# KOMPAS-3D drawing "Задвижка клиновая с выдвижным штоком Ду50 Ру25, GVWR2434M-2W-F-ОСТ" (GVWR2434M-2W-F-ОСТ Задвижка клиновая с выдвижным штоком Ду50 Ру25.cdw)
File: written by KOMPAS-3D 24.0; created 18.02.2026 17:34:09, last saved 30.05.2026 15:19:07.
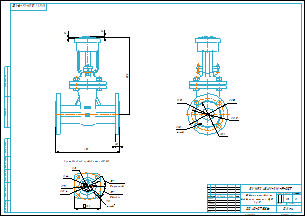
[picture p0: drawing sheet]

Document properties: Автор: R2D2; Форматы листов документа: A2; Полное имя файла: GVWR2434M-2W-F-ОСТ Задвижка клиновая с выдвижным штоком Ду50 Ру25.m3d; Масса: 13; Наименование: Задвижка клиновая с выдвижным штоком Ду50 Ру25; Количество листов документа: 1; Примечание: D040-07586

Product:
- Part/product: Задвижка клиновая с выдвижным штоком Ду50 Ру25  | designation GVWR2434M-2W-F-ОСТ
    Масса: 13
    Раздел спецификации: Прочие изделия
    Примечание: D040-07586

Views: Проекционный вид 3
Referenced files in E:\Работа\Зайцев\Для компаса\: чертеж DN.ru А3.cdt
Referenced files in E:\Работа\Зайцев\GVWR2434M-2W-F-ОСТ Задвижка клиновая с выдвижным штоком DN.ru Ду50-300 Ру25\исходные материалы\DN50\DN50\: GVWR2434M-2W-F-ОСТ Задвижка клиновая с выдвижным штоком Ду50 Ру25.m3d
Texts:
  Присоединение привода тип АК (А)
  чертеж DN.ru А3.cdt
  Задвижка клиновая с
  выдвижным штоком Ду50
  Ру25
  GVWR2434M-2W-F-ОСТ
  Задвижка клиновая с выдвижным штоком Ду50 Ру25
  GVWR2434M-2W-F-ОСТ Задвижка клиновая с выдвижным штоком Ду50 Ру25
Dimensions and other numbers on the sheet: 100; 5 кулачков; 5 впадин; 4 отв.; 104; 70; 44; 32; 1:2; 0; 1; 2; 13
